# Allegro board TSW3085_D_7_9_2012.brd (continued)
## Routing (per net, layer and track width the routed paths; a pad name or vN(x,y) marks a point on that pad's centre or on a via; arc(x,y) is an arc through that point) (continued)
TCK: length 28
  BOTTOM w0.152: J15.1 R122.1 91.95,127.64 86.92,122.61 U4.26
TDI: length 43.1
  TOP w0.152: v1(92.52,100.55) 91.85,101.22 91.85,107.04 95.03,110.22 98.16,110.22 100.33,112.4 101.35,112.4 101.36,112.38 103.15,114.17 103.15,121.21 104.47,122.53 107.37,122.53 108.86,124.03 108.86,127.72 J15.9
  BOTTOM w0.152: R129.1 109.35,128.2 J15.9
TDO: length 27.6
  TOP w0.152: J15.3 101.47,127.94 101.47,119.99 99.92,118.44 99.92,113.59 98.13,111.8 v1(91.72,111.8)
  BOTTOM w0.152: R121.1 J15.3
TMS: length 39.8
  TOP w0.152: J15.5 103.33,127.26 103.33,125.63 101.88,124.18 101.88,119.56 100.38,118.06 100.38,113.56 98.07,111.25 94.72,111.25 87.72,104.25 v1(87.72,100.55)
  BOTTOM w0.152: R125.1 J15.5
TXCCLKN: length 6.3
  TOP w0.127: U1.B3 44.3,69.46
  TOP w0.152: C3.1 R15.2 44.3,73.18 44.3,69.46
TXCCLKP: length 6.3
  TOP w0.127: 44.58,69.46 44.59,69.45 44.59,69.35 44.6,69.33 U1.A3
  TOP w0.152: C4.1 45.31,74.32 45.31,73.89 R15.1 44.58,73.15 44.58,72.87 44.78,72.67 44.78,71.53 45.01,71.3 45.01,70.94 44.58,70.51 44.58,69.46
TXEN: length 92.7
  TOP w0.152: R18.2 v1(35.69,37.59)
  BOTTOM w0.152: J13.27 3.92,94.48 2.03,92.6 2.03,40.51 5.84,36.7 12.45,36.7 13.46,37.72 35.56,37.72 v1(35.69,37.59)
TXENABLE: length 38.7
  TOP w0.152: R18.1 JP2.2
  BOTTOM w0.102: 45.2,59.23 v5(45.2,60.6)
  BOTTOM w0.152: 45.2,59.23 45.2,58.69 48.77,55.12 48.77,37.46 45.85,34.54 41.4,34.54 39.37,36.58 JP2.2
TXSP1: length 66.7
  L3_PWR w0.152: v1(12.46,94.98) 15.48,94.98 34.8,114.3 38.86,114.3 38.99,114.43 40.64,114.43 40.77,114.3 43.94,114.3 45.26,115.62 67.11,115.62 v1(68.71,117.22)
  BOTTOM w0.152: J13.26 v1(12.46,94.98)
TXSP2: length 107.6
  L3_PWR w0.152: v1(94.14,106.17) 91.82,106.17 90.42,104.78 90.42,104.04 90.14,103.76 82.93,103.76 82.17,104.52 82.17,106.43 82.68,106.93 84.45,106.93 85.34,107.82 85.34,109.98 84.07,111.25 81.66,111.25 80.16,109.75 69.82,109.75 68.45,111.12 68.45,111.98 67.73,112.7 66.3,112.7 65.69,112.09 61.33,112.09 60.17,113.25 51.22,113.25 51.07,113.4 50.56,113.4 50.42,113.54 49.78,113.54 48.51,112.27 47.4,112.27 47.37,112.29 34.12,112.29 34.02,112.4 33.66,112.4 15.36,94.1 v1(12.53,94.1)
  BOTTOM w0.152: v1(12.53,94.1) 12.15,94.48 J13.28
TXSP3: length 91.3
  TOP w0.152: R2.2 7.66,88.52 8.07,88.93 8.41,88.93 9.53,90.04 9.65,90.04 11.3,91.69 13.08,91.69 v1(13.59,92.2)
  L3_PWR w0.152: v1(82.89,108.57) 83.43,108.57 83.69,108.84 83.69,110.36 83.31,110.74 81.91,110.74 80.52,109.35 66.31,109.35 64.43,111.23 60.33,111.23 58.78,112.78 51.82,112.78 50.93,111.89 47.39,111.89 47.26,112.01 34.53,112.01 34.4,111.89 34.04,111.89 14.35,92.2 v1(13.59,92.2)
TXSP4: length 87
  TOP w0.152: R3.2 8.26,87.5 11.18,90.42 12.83,90.42 v1(13.59,91.19)
  L3_PWR w0.152: v1(13.59,91.19) 14.1,91.19 34.52,111.61 46.44,111.61 46.46,111.63 46.76,111.63 46.78,111.61 58.83,111.61 59.82,110.62 64.64,110.62 66.29,108.97 81.66,108.97 82.04,109.35 82.87,109.35 v1(82.89,109.37)
TXSP5: length 116.7
  TOP w0.152: R4.2 7.62,86.49 8.13,87 8.89,87 11.94,90.04 12.95,90.04 v1(13.59,89.41)
  L3_PWR w0.152: v1(13.59,89.41) 13.11,89.89 13.11,92.64 11.68,94.06 11.68,95.1 12.34,95.76 15.37,95.76 36.2,116.59 36.2,117.16 37.01,117.98 37.47,117.98 37.52,118.03 43.92,118.03 45.87,116.08 66.88,116.08 69.16,118.36 72.34,118.36 72.82,117.88 73.23,117.88 73.71,118.36 75.56,118.36 80.07,113.86 84.77,113.86 85.85,112.78 92.58,112.78 93.98,111.38 93.98,109.98 93.6,109.6 93.6,107.52 v1(94.14,106.97)
TXSP6: length 130.4
  TOP w0.152: R1.2 7.11,90.04 6.73,90.42 5.46,90.42 5.21,90.17 5.21,86.36 5.87,85.7 8.99,85.7 11.18,87.88 13.08,87.88 v1(13.59,88.39)
  L3_PWR w0.152: v1(13.59,88.39) 13.08,88.9 12.45,88.9 12.42,88.93 12.37,88.93 11.05,90.25 11.05,95.63 11.68,96.27 15.11,96.27 35.92,117.07 35.92,117.28 36.9,118.26 37.11,118.26 37.29,118.44 44.3,118.44 46.18,116.56 66.7,116.56 70.15,120.02 70.62,120.02 70.64,119.99 71.04,119.99 71.07,120.02 75.06,120.02 80.65,114.43 85.22,114.43 86.36,113.28 92.84,113.28 94.77,111.35 94.77,105.89 94.25,105.37 v1(94.14,105.37)
USB RESET: length 9
  TOP w0.152: U3.19 106.2,115.98 106.43,115.75 110.11,115.75 SW2.2
  BOTTOM w0.152: C50.1 109.09,112.57 109.45,112.93 109.45,113.46 SW2.2
N27288443: length 13.5
  TOP w0.216: U3.16 106.91,114.03 v1(107.82,114.94)
  BOTTOM w0.216: J14.2 111.16,122.85 109.73,121.41 109.73,116.84 v1(107.82,114.94)
N27288567: length 19.1
  L3_PWR w0.508: v2(105.84,116.61) 105.49,116.61 v2(105.48,116.63) 105.14,116.63 v2(105.13,116.64) 104.73,116.64 103.33,115.23 103.33,114.25 103,113.92 v1(101.98,113.92) ; v1(101.98,113.92) 101.98,113.79 v1(101.6,113.41) 101.6,113.28 v1(101.22,112.9) ; v1(101.98,113.92) 101.98,118.49 102.87,119.38 102.87,121.89 102.92,121.89 103.3,122.28 103.3,122.83 102.92,123.22 102.87,123.22 102.87,124.08 v1(101.98,124.97)
N27288614: length 13.4
  TOP w0.152: C97.1 96,119.88 U3.4 v1(100.03,119.89) ; v1(104.11,115.09) 104.53,114.68 U3.17
  BOTTOM w0.152: v1(100.03,119.89) 100.33,119.58 101.5,119.58 102.67,118.41 102.67,115.93 103.5,115.09 v1(104.11,115.09)
N27288630: length 14.1
  TOP w0.216: v1(107.82,113.54) 107.66,113.38 U3.15
  BOTTOM w0.216: J14.3 111.25,122.05 110.36,121.16 110.36,116.59 109.47,115.7 109.47,114.55 109.22,114.3 108.59,114.3 v1(107.82,113.54)
N27836198: length 3.4
  BOTTOM w0.508: 94.59,5.22 C153.1 94.59,7.92 FB20.2
  vias: v1(96.11,8.69) v1(96.11,7.8) v1(96.75,8.94) v1(96.75,8.18) v1(97.51,8.94) v1(97.51,8.18)
N28086696: length 2.9
  TOP w0.305: 67.23,9.8 67.23,10.69 67.48,10.94 U22.1 ; U22.3 67.4,9.64
  TOP w0.508: 67.4,9.64 67.23,9.8
  vias: v2(60.99,11.07) v2(60.99,9.75) v2(61.31,11.06) v2(61.32,9.75) v3(43.1,5.64) v3(44.04,6.02) v3(45.82,7.24) v3(45.97,5.97) v3(47.35,8.43) v3(48.44,8) v3(49.07,8.38) v3(49.78,9.4) v3(50.19,7.98) v3(50.55,10.16) v3(50.83,8.38) v3(51.94,10.29) v3(52.7,9.78) v3(59.31,9.12) v3(60.71,9.02) v3(61.09,8.25) v3(61.09,7.37) v3(62.1,7.24) v3(63.25,7.62) v3(64.08,7.16) v3(64.44,7.82)
N28167010: length 3
  TOP w0.495: L3.1 C184.1 C197.2 R277.1
N28167020: length 3
  TOP w0.495: R278.1 C192.1 C184.2 L4.1
N28168739: length 3
  TOP w0.305: L1.1 C205.1 C200.2 R280.1
N28168741: length 3
  TOP w0.305: R279.1 C220.1 C205.2 L2.1
N28168902: length 3
  TOP w0.305: R303.1 C221.1 C206.2 R279.2
N28168904: length 3
  TOP w0.305: R280.2 C206.1 C217.2 R302.1
N30175128: length 4.4
  TOP w0.508: R257.2 63.14,11.94
  TOP w1.016: R128.2 62.99,13.72
N30185572: length 2.1
  TOP w0.305: R221.2 69.95,11.66
N31066293: length 3
  TOP w0.495: R296.1 C198.2 C186.1 R277.2
N31066982: length 3
  TOP w0.495: R297.1 C193.1 C186.2 R278.2
N33713354: length 2
  TOP w0.152: 49.4,72.26 C35.1 ; 49.4,72.26 R133.1 ; 49.4,72.26 R43.1
N33713380: length 1
  TOP w0.152: C34.1 R43.2
N33713396: length 4.1
  TOP w0.102: U1.A1 45.8,69.29 46.23,69.72 48.23,69.72 48.46,69.95
  TOP w0.152: 48.46,69.95 48.74,70.23 R133.2
N33713852: length 1
  BOTTOM w0.152: R44.2 R45.1
N33713873: length 4.3
  TOP w0.102: 45.8,59.55 45.8,59.23
  TOP w0.127: U1.A33 45.8,60.08 45.86,60.02 45.86,59.61 45.8,59.55
  TOP w0.152: v1(45.69,57.1) 45.8,57.2 45.8,59.23
  BOTTOM w0.152: v1(45.69,57.1) 46.13,56.67 R44.1
N33714300: length 65.2
  TOP w0.102: U1.B40 46.45,68.17 46.61,68.33 v1(48.26,68.33)
  TOP w0.152: v1(57.15,54.1) 57.28,53.98 57.28,51.82 53.85,48.39 53.85,36.45 52.83,35.43 34.8,35.43 33.66,36.58 JP3.2
  L3_PWR w0.102: 48.46,68.33 v1(48.26,68.33)
  L3_PWR w0.152: 48.46,68.33 49.02,68.33 49.4,67.95 49.4,63.37 50.42,62.36 50.8,62.36 51.05,62.1 51.05,59.84 51.21,59.69 51.56,59.69 v1(57.15,54.1)
N33806169: length 1.1
  TOP w0.305: R313.1 v1(83.19,63.91)
N33840412: length 0.9
  TOP w0.305: 91.06,67.72 91.51,67.26 U23.24
N33892115: length 0.4
  TOP w0.305: U23.18 94.77,66.25 95.05,66.52
N33970284: length 3
  TOP w0.305: R12.2 72.02,9.64 U22.4
  TOP w0.508: R12.2 R221.1
N33977043: length 2.9
  TOP w0.508: R257.1 R10.2 64.88,9.76 U13.4
N34062669: length 2.3
  TOP w0.305: C259.2 84.73,64.44 C132.2 R174.1
N34111815: length 2
  TOP w0.305: U14.6 75.88,6.8 C113.1
N34113396: length 3.3
  TOP w0.305: R159.2 76.33,13.72 76.33,13.21 75.88,12.76 U14.3
N34242338: length 2.2
  TOP w0.305: C119.1 85.4,6.33 U18.6
N34242397: length 3
  TOP w0.305: U18.3 85.4,13.41 R171.2 R176.1
N34261747: length 2.8
  TOP w0.216: R107.2 106.84,57.19 v1(106.46,57.19)
  BOTTOM w0.254: v1(106.46,57.19) 106.7,57.19 106.73,57.15 107.17,57.15 107.21,57.19 U7.3
N34261766: length 8.3
  BOTTOM w0.254: U7.2 106.98,56.69 106.8,56.51 106.8,54.75 107.44,54.1 108.2,54.1 108.76,53.55 C175.1
  BOTTOM w0.495: C175.1 108.61,52.83 C176.1
  BOTTOM w0.762: FB23.1 C176.1
N34261843: length 7.2
  BOTTOM w0.495: C256.1 105.97,54.25 C251.1 C110.1 105.71,56.09 104.32,57.48 L5.1
  BOTTOM w0.762: R293.2 C256.1
N34261894: length 9.8
  TOP w0.216: 113.28,57.15 112.39,57.15 111.38,56.13 108.97,56.13 107.41,57.69 v1(106.95,57.69)
  TOP w0.254: v1(113.32,57.19) 113.18,57.05 R108.2
  BOTTOM w0.254: U7.4 v1(106.95,57.69) ; U7.22 v1(113.32,57.19)
N34318237: length 4.1
  TOP w0.216: 49.05,110.19 48.17,109.31 U16.42
  TOP w0.495: 49.05,110.19 49.05,110.49 C127.1 49.36,112.28 C107.1
N34318365: length 3.6
  TOP w0.216: 42.29,100.71 42.42,100.71
  TOP w0.254: 42.42,100.71 43.11,101.41 U16.11
  TOP w0.305: 42.29,100.71 42.04,100.71 41.33,100.01 40.11,100.01
N34318369: length 2.9
  TOP w0.152: 42.82,100.42 42.82,100.36
  TOP w0.254: U16.12 42.82,100.42
  TOP w0.305: C52.1 42.29,100.08 42.55,100.08 42.82,100.36
N34318504:
  vias: v1(30.61,97.84)
N34318582: length 22.6
  BOTTOM w0.152: R11.2 33.5,102.44 34.19,103.12 35.43,103.12 37.92,100.63 40.36,100.63 44.83,105.11 48.74,105.11 49.05,105.41 50.65,105.41 v2(51.36,106.12)
N34318594: length 13.4
  TOP w0.254: v1(39.34,107.06) 39.93,106.48 U16.63
  BOTTOM w0.152: R9.2 31.57,100.71 31.57,103 32.69,104.11 35.28,104.11 38.23,107.06 v1(39.34,107.06)
N34318598: length 19.8
  BOTTOM w0.152: v2(40.28,106.83) 40.28,106.91 39.45,107.75 38.35,107.75 36.37,105.77 35.51,105.77 35.18,106.1 32.74,106.1 29.74,103.1 29.74,99.75 30.51,98.98 31.09,98.98 R8.2
N34318724: length 4.9
  BOTTOM w1.016: FB2.2 63.09,125.04 62.26,124.21 62.26,123.85 60.45,122.05
N34318773: length 3
  TOP w0.152: U16.37 49.94,107.54 50.47,108.07 50.47,108.3 C77.2
N34318798:
  vias: v2(45.95,99.75) v2(46.18,99.52) v2(46.3,100.1) v2(46.53,99.9)
N34318866:
  vias: v2(39.45,106.25) v2(39.67,106.02)
N34318908: length 2.3
  TOP w0.305: Y1.2 R274.2
N34318943: length 4.4
  TOP w0.305: SJP5.2 R72.1 R70.2 72.01,121.23 U26.1
N34319037: length 11.5
  TOP w0.381: U26.6 v1(67.52,122.63) ; U26.2 v1(70.29,121.98)
  TOP w0.495: FB8.1 74.93,124.08 C303.1 C302.1 74.87,121.98 U26.2
  BOTTOM w0.381: v1(67.52,122.63) 69.64,122.63 v1(70.29,121.98)
N34319101: length 5.7
  TOP w0.305: R273.2 57.91,109.73 R62.2 R61.2 60.9,109.73 Y1.1
N34319133: length 5.6
  TOP w0.305: R61.1 59.56,112.59 Y1.6
  vias: v1(62.87,117.6) v1(62.87,117.04) v1(63.53,117.04) v1(63.83,117.58)
N34319167: length 3
  TOP w0.305: R54.1 67.88,115.95 67.18,115.25
N34319169: length 1.1
  TOP w0.305: R54.2 SJP5.3
N34319278:
  vias: v1(30.61,100.1)
N34319280:
  vias: v1(30.61,102.41)
N34319320:
  vias: v1(44.3,113.18) v1(44.37,113.77) v1(45.26,114.71) v1(45.93,114.82) v2(41.94,108.74) v2(42.11,108.53) v2(43.69,110.52) v2(43.87,110.34) v2(46.4,111.08) v2(46.61,111.28)
N34319417:
  vias: v2(48.64,109.07)
N34319628: length 2.8
  TOP w0.152: C78.2 51.17,100.9 49.24,102.83 U16.26
N34337938: length 1.8
  TOP w0.152: v1(103.66,124.97) D3.1
  BOTTOM w0.152: R40.2 v1(103.66,124.97)
N34338940: length 9.6
  BOTTOM w0.61: FB26.1 100.03,114.88 101.32,114.88 101.98,115.54 101.98,117.48 101.41,118.04 U6.5 98.9,118.04 C8.1
N34339153: length 4.7
  BOTTOM w0.508: SJP3.2 104.62,112.98 104.62,113.03 104.9,113.31 104.9,115.8 104.56,116.14 U6.3
N34340024: length 10.4
  BOTTOM w0.152: J14.4 114.19,121.25 114.4,121.46 114.4,123.93 113.82,124.51 109.8,124.51 R117.1
N34341306: length 16.8
  BOTTOM w0.152: U4.35 95.25,109.37 95.5,109.63 95.5,111.68 94.13,113.06 94.13,117.96 91.04,121.06 90.53,121.06 89.92,121.67 U5.2
N34341363: length 22.2
  TOP w0.152: v1(95.76,120.65) 95.88,120.53 U3.3
  BOTTOM w0.152: U4.43 95.66,102.97 96.32,103.63 96.32,120.09 v1(95.76,120.65)
N34341376: length 20.9
  TOP w0.152: v1(85.74,106.97) 85.98,107.21 85.98,110.72 87.26,112 87.26,112.03 87.53,112.3 87.56,112.3 88.54,113.28 94.62,113.28 R20.1 96.66,115.33 U3.11
  BOTTOM w0.152: U4.18 v1(85.74,106.97)
N34341390: length 22.9
  TOP w0.152: v1(84.48,107.77) 84.02,108.23 84.02,113.35 84.98,114.3 92.61,114.3 94.31,116 95.3,116 R22.1 95.93,116.63 U3.9
  BOTTOM w0.152: U4.19 v1(84.48,107.77)
N34341426: length 24.8
  TOP w0.152: v1(95.76,121.67) 96.25,121.18 U3.2
  BOTTOM w0.152: U4.44 94.18,102.21 95.78,102.21 96.8,103.23 96.8,115.04 96.62,115.21 96.62,118.92 96.8,119.1 96.8,120.65 95.78,121.67 v1(95.76,121.67)
N34341471: length 4.3
  BOTTOM w0.152: v1(92.58,117.48) 91.31,117.48 90.91,117.08 90.91,117.07 90.61,116.76 90.47,116.76 89.92,116.21 U5.7
N34341475: length 15.2
  BOTTOM w0.152: U5.1 88.65,121.08 91.69,118.03 92.71,118.03 93.07,117.68 93.07,117.33 93.57,116.82 93.57,112.8 93.37,112.6 93.37,111.53 94.14,110.76 U4.34
N34341497: length 8.3
  BOTTOM w0.152: U5.3 91.19,123.8 91.77,124.38 96.82,124.38 v1(97.54,125.1)
N34341585: length 16.3
  TOP w0.152: v1(84.52,113.19) 85.12,113.79 92.68,113.79 93.85,114.96 95.17,114.96 95.66,115.44 R23.1 96.29,115.98 U3.10
  BOTTOM w0.152: U4.23 v1(84.52,113.19)
N34341705: length 20.4
  TOP w0.152: U3.6 96.7,118.58 96.24,118.12 96.24,118.08 v1(95.76,117.6) 95.17,117.02 94.01,117.02 92.8,115.81 85.92,115.81 82.89,112.79 v1(82.89,110.17)
N34341779: length 38.6
  TOP w0.152: v1(91.72,100.55) 91.21,101.05 91.21,107.04 94.86,110.68 98.01,110.68 102.64,115.32 v1(102.64,122.56) ; U3.1 96.61,121.83 v1(95.76,122.68)
  BOTTOM w0.152: v1(102.64,122.56) 102.51,122.68 v1(95.76,122.68)
N34341783: length 19.4
  TOP w0.152: U3.5 96.37,119.23 v1(95.76,118.62)
  BOTTOM w0.152: v1(95.76,118.62) 95.71,118.62 95.28,118.19 95.28,112.57 95.88,111.96 95.88,104.39 95.28,103.78 94.16,103.78 U4.42
N34538813: length 28.3
  BOTTOM w0.152: U4.37 86.94,107.77 77.5,117.22 v1(69.72,117.22)
N34674399: length 8.1
  TOP w0.305: U11.4 37.6,14.92 37.21,14.53 v3(36.68,14.53)
  BOTTOM w0.305: v3(40.49,9.96) 39.85,10.59 39.85,11.35 v3(36.68,14.53)
N34674443: length 7.5
  TOP w0.305: v1(38.46,16.94) 38.46,16.44 U11.1 ; R153.2 v1(39.6,21.36) C166.2 R150.1
  BOTTOM w0.305: v1(39.6,21.36) 39.6,18.21 38.46,17.07 v1(38.46,16.94)
N34674591: length 1.3
  TOP w0.305: 42.42,13.72 41.72,14.42 U11.6
N34674628:
  vias: v1(55.85,13.44) v1(55.85,12.65) v1(55.88,14.22) v1(55.88,11.81) v1(55.88,11.05) v4(54.33,10.24) v4(55.98,10.21)
N34674653: length 3.1
  TOP w0.305: U11.5 37.79,14.42 36.88,13.51 R148.1 R151.2
N34674671: length 2.5
  TOP w0.508: U12.5 57.12,13.11 57.35,12.88 C162.1
N34674884: length 0.9
  TOP w0.305: 112.01,108.33 112.25,108.57 U2.3
N34674940: length 2.8
  TOP w0.508: C215.1 98.55,106.3 99.31,105.54 U15.5
N34708918: length 1.5
  BOTTOM w0.152: J13.175 6.32,47.47 v1(6.6,47.75)
N34708920: length 1.5
  BOTTOM w0.152: v1(6.6,46.74) 6.37,46.97 J13.177
N34708959: length 2.5
  TOP w0.152: v1(6.81,95.86) R6.1
  BOTTOM w0.152: v1(6.81,95.86) 6.68,95.98 J13.21
N34714738: length 1.3
  BOTTOM w0.152: J13.38 12.35,91.98 v1(12.57,92.2)
N34714741: length 1.3
  BOTTOM w0.152: J13.40 12.28,91.48 v1(12.57,91.19)
N34722561: length 1.4
  BOTTOM w0.152: J13.50 12.14,88.98 v1(12.57,89.41)
N34722570: length 1.3
  BOTTOM w0.152: v1(12.57,88.39) 12.49,88.48 J13.52
N34728902: length 1.1
  BOTTOM w0.152: J13.47 v1(6.29,89.48)
N34729206: length 1.4
  TOP w0.152: R2.1 6.14,88.48 v1(6.31,88.48)
  BOTTOM w0.152: J13.51 v1(6.31,88.48)
N34729215: length 1.5
  BOTTOM w0.152: v1(6.35,87.5) 6.35,87.76 6.13,87.98 J13.53
N34729224: length 1.2
  BOTTOM w0.152: J13.59 v1(6.34,86.48)
N34783131: length 1.6
  BOTTOM w0.381: U6.4 98.89,116.14 C7.1
N34841492: length 3.6
  TOP w0.508: U21.4 102.92,13.71 103.16,13.46 Q1.3
N278362830: length 2.5
  TOP w0.254: D2.1 92.3,8.94 v1(93.32,8.94)
  BOTTOM w0.254: R143.1 v1(93.32,8.94)
N343181311: length 1.1
  TOP w0.495: R89.1 50.82,112.28 C127.2
N343181471: length 1.1
  TOP w0.305: C177.2 54.83,108.22 R90.1
N346744130: length 3.2
  TOP w0.305: L26.1 43.39,16.42 U11.10

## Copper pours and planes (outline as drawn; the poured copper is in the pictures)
6VIN on TOP: 2.54,99.7 2.54,107.95 19.05,107.95 19.05,102.87 12.7,102.87 12.7,99.7
6VIN on L3_PWR: 2.54,99.7 2.54,109.86 19.05,109.86 19.05,102.87 12.7,102.87 12.7,99.7
+1.2VCLK on TOP (solid shape): 68.07,31.62 68.07,23.88 64.9,23.88 64.9,30.48 63.5,31.88 63.5,33.15 64.26,33.91 65.79,33.91
+1.2VCLK on L3_PWR: 62.23,51.1 53.23,60.11 53.23,62.42 53.19,62.46 49.43,62.46 49.43,69.09 43.81,69.09 43.56,69.34 43.56,70.61 43.31,70.87 43.31,72.52 42.42,73.41 40.89,73.41 40.89,75.18 42.67,75.18 46.1,71.76 54.48,71.76 67.94,58.29 67.94,25.4 62.23,25.4
+1.2VD on TOP: 35.81,23.37 35.81,29.72 40.26,29.72 40.26,26.67 38.35,26.67 38.35,23.37
+1.2VD on L3_PWR: 34.29,23.24 34.29,60.07 38.1,63.88 38.1,75.57 40.64,75.57 40.64,71.76 43.18,71.76 43.18,70.26 43.15,70.23 43.31,70.23 43.31,69.09 43.15,68.94 43.15,68.12 42.85,67.82 42.85,60.12 44.83,58.14 44.83,57.45 44.45,57.45 44.45,23.24
+1.2VDAC on TOP (solid shape): 60.83,28.32 60.83,24.89 63.12,24.89 63.12,23.11 58.29,23.11 58.38,27.31 58.16,27.31 56.9,28.57 56.9,29.72 57.66,30.48 58.67,30.48
+1.2VDAC on L3_PWR: 43.43,60.58 46.74,57.28 46.74,51.05 52.7,45.09 52.7,25.4 60.96,25.4 60.96,49.58 51.44,59.11 50.11,59.11 50.55,59.54 50.55,61.77 49.73,62.59 48.88,62.59 48.88,67.58 47.62,68.83 43.56,68.83 43.43,68.71
+3.3V_MOD1 on TOP (solid shape): 77.6,24.13 74.04,24.13 74.04,30.23 77.6,30.23
+3.3V_MOD1 on TOP (solid shape): 78.23,65.56 78.49,65.3 78.49,63.4 77.34,63.4 77.34,65.43 77.47,65.56 77.47,66.06 78.23,66.06
+3.3V_MOD1 on L3_PWR: 69.22,49.66 69.22,59.69 66.55,62.36 66.55,85.6 66.68,85.73 91.19,85.73 91.31,85.6 91.31,80.14 71.25,80.14 71.12,80.01 71.12,66.68 73.03,64.77 76.07,64.77 77.09,65.79 78.99,65.79 78.99,61.21 75.95,61.21 75.95,49.78 77.98,47.75 77.98,25.4 72.14,25.4 72.14,46.74
+3.3V_MOD2 on TOP (solid shape): 103.66,68.73 102.39,68.73 102.39,70.51 103.66,70.51
+3.3V_MOD2 on TOP (solid shape): 82.93,24.13 79.38,24.13 79.38,30.23 82.93,30.23
+3.3V_MOD2 on L3_PWR: 79.38,76.58 79.38,76.2 77.47,76.2 77.47,50.16 79.38,48.26 79.38,25.4 84.45,25.4 84.45,72.52 95.88,72.52 96.77,71.63 96.77,67.06 104.01,67.06 104.01,72.64 101.22,72.64 100.58,73.28 100.58,73.41 97.41,76.58
+3.3VA on L6_PWR: 49.28,70.87 49.15,70.74 49.15,67.06 45.85,67.06 45.92,66.98 45.92,59.26 47.62,57.56 47.62,9.53 58.04,9.53 58.04,41.66 58.8,42.42 58.8,66.17 62.23,69.6 62.23,76.2 60.58,77.85 56.52,77.85 55.37,76.71 55.37,71.25 54.99,70.87
+3.3VCLK on TOP: 100.97,111 100.97,103.51 100.2,103.51 100.2,106.93 100.08,107.06 99.57,107.06 99.57,111
+3.3VCLK on L6_PWR: 118.11,134.62 118.11,73.03 66.68,73.03 65.72,73.98 65.72,74.49 61.21,78.99 50.93,78.99 49.28,77.34 49.28,74.3 41.91,74.3 29.21,87 29.21,134.62 ; 2 cut-outs
+3.3VD on BOTTOM (solid shape): 45.34,26.92 42.42,26.92 42.42,30.28 45.34,30.28
+3.3VD on TOP: 41.66,26.54 41.66,33.66 44.45,33.66 44.45,26.54
+3.3VD on L6_PWR: 37.97,32.89 41.91,28.96 41.91,24.77 46.1,24.77 46.1,57.39 42.93,60.56 42.93,68.96 39.88,68.96 37.97,67.06
+3.3VRF on TOP (solid shape): 83.31,15.37 82.55,14.61 81.41,14.61 78.23,11.43 76.45,11.43 76.45,12.19 77.09,12.83 77.09,14.1 76.58,14.61 76.58,17.65 75.18,17.65 74.04,18.8 74.04,21.34 83.31,21.34
+3.3VRF on L6_PWR: 118.11,50.04 118.11,55.12 117.22,56.01 112.78,56.01 112.4,55.63 112.4,55.12 109.22,55.12 108.33,56.01 105.66,56.01 103.63,58.04 90.81,58.04 88.9,59.94 80.01,59.94 79.95,60.01 67.63,60.01 62.99,55.37 62.99,23.24 74.17,12.07 84.45,12.07 84.45,19.05 76.84,19.05 72.33,23.56 72.33,38.54 72.26,38.61 72.26,49.78 92.87,49.78 94.27,51.18 108.08,51.18 108.08,49.91 113.28,49.91 113.41,50.04
+3.6V on TOP (solid shape): 113.03,109.86 112.01,109.86 111.38,109.22 108.08,109.22 108.08,110.49 113.03,110.49
+5V_MOD1 on TOP (solid shape): 89.92,24.13 86.61,24.13 86.61,30.23 89.92,30.23
+5V_MOD1 on L3_PWR: 90.17,55.12 95.88,60.83 95.88,70.87 85.09,70.87 85.09,25.4 90.17,25.4
+5V_MOD2 on TOP (solid shape): 95.25,24.13 91.95,24.13 91.95,30.23 95.25,30.23
+5V_MOD2 on TOP (solid shape): 76.33,67.59 76.71,67.59 76.71,66.83 76.2,66.83 75.95,66.57 74.17,66.57 74.17,67.84 76.07,67.84
+5V_MOD2 on TOP (solid shape): 103.38,73.43 103.12,73.18 103.12,72.92 102.36,72.92 102.36,73.3 102.11,73.56 102.11,75.34 103.38,75.34
+5V_MOD2 on L3_PWR: 104.9,67.06 104.9,73.03 101.85,73.03 101.73,73.15 101.73,74.17 98.43,77.47 76.71,77.47 76.71,66.17 75.95,65.41 73.03,65.41 71.75,66.68 71.75,79.63 71.88,79.76 94.36,79.76 97.16,82.55 103.5,82.55 109.22,76.84 109.22,65.02 105.16,60.96 105.16,52.96 96.9,44.7 96.9,25.4 91.31,25.4 91.31,53.47
+5VA_MOD on TOP (solid shape): 95.63,12.95 89.66,12.95 88.01,11.3 86.11,11.3 86.11,11.94 87.12,12.95 87.12,13.97 86.61,14.48 86.61,17.02 85.85,17.78 85.85,21.34 95.63,21.34
+5VA_MOD on L6_PWR: 94.74,13.34 88.27,13.34 88.27,19.05 90.81,19.05 99.06,27.3 99.06,46.61 103,50.55 106.93,50.55 106.93,47.62 105.28,45.97 105.28,23.88
+6V on TOP (solid shape): 117.63,108.18 114.86,108.18 114.86,109.22 117.63,109.22
+6V on TOP (solid shape): 75.31,7.87 73.66,6.22 72.64,6.22 72.64,7.49 73.41,7.49 74.8,8.89 75.31,8.89
+6V on TOP (solid shape): 80.01,6.6 78.74,6.6 78.74,7.49 78.61,7.62 76.71,7.62 76.45,7.87 76.45,8.89 80.01,8.89
+6V on TOP (solid shape): 84.84,7.87 84.2,7.24 81.53,7.24 81.53,8.25 83.69,8.25 84.2,8.76 84.84,8.76
+6V on TOP (solid shape): 89.79,6.6 88.52,6.6 88.52,7.75 86.33,7.75 86.11,7.98 86.11,8.76 89.79,8.76
+6V on TOP (solid shape): 34.16,16.64 35.18,16.64 35.43,16.38 37.08,16.38 37.59,15.88 38.73,15.88 38.73,15.49 37.21,15.49 37.08,15.37 32.38,15.37 32.38,16.89 33.91,16.89
+6V on TOP: 92.96,10.8 92.96,13.34 97.03,13.34 96.96,13.27 96.96,11.62 96.14,10.8
+6V on TOP: 106.68,119.38 106.68,116.97 109.22,116.97 109.22,119.38
+6V on TOP: 79.76,8.25 79.76,7.24 83.31,7.24 83.31,8.25
+6V on BOTTOM: 92.46,10.54 92.46,13.59 97.16,13.59 97.16,10.54
+6V on BOTTOM: 41.15,16.13 41.15,14.61 42.8,14.61 42.8,16.13
+6V on BOTTOM: 32.38,16.89 32.38,15.11 38.61,15.11 38.61,16.13 37.47,16.13 37.47,16.89
+6V on BOTTOM: 105.28,112.01 105.28,117.09 103.12,117.09 103.12,119.38 108.97,119.38 108.97,117.09 107.44,117.09 107.44,112.01
+6V on BOTTOM: 72.01,8.89 72.01,5.46 90.04,5.46 90.04,8.89
+6V on BOTTOM: 114.43,109.47 114.43,107.57 117.86,107.57 117.86,109.47
+6V on L3_PWR: 118.11,119.38 118.11,2.54 66.04,2.54 66.04,12.7 52.7,12.7 50.93,14.48 46.61,14.48 44.83,12.7 41.27,12.7 41.27,10.8 29.21,10.8 29.21,21.59 45.72,21.59 45.72,24.13 105.54,24.13 105.54,42.04 111.76,48.26 111.76,111.76 105.16,111.76 105.16,113.84 106.5,115.19 106.5,117.35 103.5,117.35 103.5,119.38
GNDA on TOP (solid shape): 67.57,112.01 68.07,112.01 68.07,110.24 66.55,110.24 66.55,111.26 65.97,111.26 65.97,112.55 67.57,112.55
GNDA on TOP: 56.52,124.46 56.52,106.68 74.93,106.68 74.93,124.46 ; 1 cut-out
GNDA on TOP: 66.68,133.98 66.68,121.29 90.17,121.29 90.17,133.98
GNDA on TOP: 0.64,82.55 0.64,111.12 8.26,118.75 27.3,118.75 27.3,136.53 120.02,136.53 120.02,82.55 ; 10 cut-outs
GNDA on TOP: 27.3,0.64 27.3,29.34 8.51,29.34 0.64,37.21 0.64,82.55 4.45,82.55 4.45,45.72 35.43,45.72 46.36,56.64 50.29,56.64 52.07,58.42 52.07,76.45 39.12,76.45 32.77,82.8 51.82,82.8 52.07,82.55 120.02,82.55 120.02,70.48 120.52,70.48 120.52,66.17 120.02,66.17 120.02,64.14 120.52,64.14 120.52,59.94 120.02,59.94 120.02,0.64 ; 3 cut-outs
GNDA on BOTTOM: 8.26,118.75 27.05,118.75 27.05,136.78 120.4,136.78 120.4,132.33 120.27,132.33 120.27,83.95 120.02,83.95 120.02,81.92 120.27,81.92 120.27,67.18 120.02,67.18 120.02,63.12 120.27,63.12 120.27,0.38 27.05,0.38 27.05,29.34 8.38,29.34 8.38,29.46 0.64,37.21 0.64,111.12 ; 4 cut-outs
GNDA on L2_GND, L5_GND, L7_GND: 8.26,118.75 27.05,118.75 27.05,136.78 120.4,136.78 120.4,132.33 120.27,132.33 120.27,83.95 120.02,83.95 120.02,81.92 120.27,81.92 120.27,67.18 120.02,67.18 120.02,63.12 120.27,63.12 120.27,0.38 27.05,0.38 27.05,29.34 8.51,29.34 0.64,37.21 0.64,111.12
GNDA on L3_PWR: 56.77,98.81 56.77,86.74 110.87,86.74 110.87,98.81
GNDA on L3_PWR: 27.81,136.14 27.81,120.27 119.38,120.27 119.38,136.14
GNDA on L3_PWR: 3.05,80.65 3.05,34.8 7.37,30.48 31.88,30.48 31.88,80.65
GNDA on L4_GND: 8.26,118.75 27.05,118.75 27.05,136.78 120.4,136.78 120.4,132.33 120.27,132.33 120.27,83.95 120.02,83.95 120.02,81.92 120.27,81.92 120.27,67.18 120.02,67.18 120.02,63.12 120.27,63.12 120.27,0.38 27.05,0.38 27.05,29.34 8.51,29.34 0.64,37.21 0.64,111.12
IN-1 on TOP (solid shape): 83.07,71.84 81.42,69.65 81.21,69.87 81.37,70.41 82.83,71.86
IP-1 on TOP (solid shape): 82.99,72.14 82.75,72.13 81.33,73.54 81.33,74.22 81.42,74.22
PLLAVDD on L6_PWR: 45.34,67.95 45.34,69.47 44.45,70.36 44.45,73.53 44.7,73.79 50.93,73.79 50.93,75.57 52.96,77.6 54.86,77.6 54.86,71.37 54.74,71.25 48.64,71.25 48.64,67.95
PWR_IN on TOP (solid shape): 18.77,96.93 13.84,96.93 13.84,101.17 18.77,101.17
PWR_IN on TOP: 109.6,13.31 105.66,17.25 101.22,17.25 101.22,14.73 104.01,14.73 104.01,10.67 99.57,10.67 98.93,10.03 98.93,8 99.31,8 99.31,3.81 107.82,3.81 109.6,5.59
PWR_IN on BOTTOM: 100.97,16.64 103.12,16.64 103.12,10.8 101.47,9.14 101.47,4.19 99.31,4.19 99.31,10.92 100.97,12.57
PWR_IN on L6_PWR: 40.64,8.25 40.64,27.94 36.07,32.51 36.07,39.5 11.63,39.5 7.95,43.18 7.95,82.88 9.53,84.46 16.51,84.46 16.51,116.84 7.37,116.84 2.54,112.01 2.54,37.46 9.53,30.48 29.21,30.48 29.21,2.54 32.51,2.54 33.4,1.65 107.57,1.65 107.57,2.54 118.11,2.54 118.11,8.25 111,8.25 111,11.43 107.57,14.86 106.55,14.86 104.39,17.02 101.09,17.02 98.93,14.86 98.93,8.25
QN-1 on TOP (solid shape): 83.04,58.48 82.81,58.45 81.26,60.03 81.31,60.63 81.42,60.63
QP-1 on TOP (solid shape): 82.98,58.19 81.42,56.06 81.14,56.06 81.19,56.61 82.77,58.24
N27836198 on BOTTOM (solid shape): 97.76,6.15 95.99,6.15 95.99,3.48 94.34,3.48 94.34,9.19 97.76,9.19
N27836198 on TOP: 97.66,12.57 98.3,12.57 98.3,12.95 102.11,12.95 102.49,12.57 102.49,10.92 101.09,10.92 100.84,11.18 99.42,11.18 98.17,9.93 98.17,6.99 95.2,6.99 95.2,10.11
N28086696 on TOP (solid shape): 67.41,9.7 68.58,9.7 68.58,9.37 66.83,7.62 66.83,6.88 66.8,6.88 66.8,6.86 60.83,6.86 60.58,7.11 60.58,8.51 60.52,8.57 59.12,8.57 58.93,8.76 58.93,9.53 60.33,9.53 60.58,9.78 61.72,9.78 61.72,8.25 61.85,8.13 65.79,8.13 65.79,9.91 67.21,9.91
N28086696 on TOP: 51.16,8 51.16,7.44 48.08,7.44 45.97,5.33 42.75,5.33 42.75,6.38 45.01,6.38 45.19,6.55 45.19,7.77 46.89,7.77 47.04,7.92 47.04,8.74 48.39,8.74 50.83,11.18 50.83,11.2 51.56,11.94 51.56,14.35 53.72,14.35 53.72,11.43 53.34,11.05 53.34,9.4 51.94,8
N28086696 on L3_PWR: 42.55,2.54 42.55,11.43 44.45,11.43 46.99,13.97 50.16,13.97 52.7,11.43 64.77,11.43 64.77,2.54
N30175128 on TOP (solid shape): 63.5,14.35 63.63,14.22 63.63,10.92 62.71,10.92 62.71,12.85 62.48,13.08 62.48,17.91 59.82,17.91 59.82,19.56 63.5,19.56
N30185572 on TOP (solid shape): 70.48,10.8 69.44,10.8 69.44,18.19 70.48,18.19
N33840412 on TOP (solid shape): 85.95,68.88 89.26,68.88 90.2,67.94 91.08,67.94 91.44,67.59 91.44,66.95 91.06,67.33 89.84,67.33 88.95,68.22 83.16,68.22 81.77,66.83 77.47,66.83 77.47,67.72 81.41,67.72 83.08,69.39 84.53,69.39 84.53,69.8 85.95,69.8
N33892115 on TOP (solid shape): 103.12,71.27 102.36,71.27 101.98,70.89 101.98,70.03 100.33,70.03 99.31,69.01 99.31,68.5 96.65,68.5 96.39,68.25 96.39,67.51 95.12,66.24 94.54,66.24 94.51,66.32 96.01,67.82 96.01,68.5 96.77,69.27 97.92,69.27 100.2,71.55 101.24,71.55 101.73,72.03 103.12,72.03
N34123238 on TOP (solid shape): 68.45,16.89 66.8,16.89 66.17,16.26 66.17,15.24 64.77,15.24 64.77,20.45 68.45,20.45
N34318798 on BOTTOM (solid shape): 47.36,99.96 45.75,98.35 45.75,97.59 46.47,96.86 45.62,96.01 45.39,96.01 44.42,96.98 44.42,97.05 42.42,99.06 43.43,100.08 44.72,98.79 46.61,100.69 46.63,100.69
N34318866 on BOTTOM (solid shape): 40.06,106.1 39.62,105.66 39.62,105.28 36.96,102.62 35.75,103.82 38.48,106.55 39.6,106.55
N34319101 on TOP (solid shape): 63.57,111.26 62.99,111.26 62.99,110.24 61.47,110.24 61.47,112.01 61.97,112.01 61.97,112.55 63.57,112.55
N34319133 on TOP (solid shape): 64.11,117.86 64.11,117.22 62.99,116.1 62.99,115.05 63.57,115.05 63.57,113.76 61.97,113.76 61.97,114.3 61.47,114.3 61.47,116.48 61.72,116.48 62.59,117.35 62.59,117.88 64.08,117.88
N34319133 on BOTTOM (solid shape): 64.8,120.73 64.08,120.73 64.08,116.79 62.59,116.79 62.59,121.89 64.8,121.89
N34319167 on TOP (solid shape): 68.07,114.3 67.57,114.3 67.57,113.76 65.97,113.76 65.97,115.05 66.55,115.05 66.55,116.08 68.07,116.08
N34319320 on BOTTOM (solid shape): 47.12,114.94 45.59,113.41 45.59,112.65 46.96,111.28 46.46,110.77 45.59,111.63 45.34,111.63 42.48,108.78 42.55,108.71 42.55,108.59 42.16,108.2 41.53,108.84 44.2,111.51 44.2,112.01 43.18,113.03 43.18,113.16 45.97,115.95 46.1,115.95
N34319417 on BOTTOM (solid shape): 51.56,109.98 50.42,108.84 49.78,109.47 49.66,109.47 48.77,108.59 48.26,109.09 49.15,109.98 49.15,110.11 47.5,111.76 48.64,112.9
N34674333 on TOP (solid shape): 42.55,20.7 45.97,20.7 45.97,18.8 42.16,18.8 42.16,18.41 40.77,18.41 40.77,25.02 42.55,25.02
N34674399 on TOP (solid shape): 46.02,10.77 44.37,10.77 44.37,8.89 40.16,8.89 40.16,12.14 46.02,12.14
N34674591 on TOP (solid shape): 45.97,13.08 41.15,13.08 41.15,14.35 45.97,14.35
N34674628 on TOP: 53.98,10.8 55.5,10.8 55.5,14.48 56.26,14.48 56.26,10.8 56.64,10.8 56.64,9.65 53.85,9.65 53.85,10.67
N34674628 on BOTTOM: 48.26,30.73 48.26,26.8 51.44,23.62 51.44,9.78 57.4,9.78 57.4,24.38 51.05,30.73
N34674884 on TOP (solid shape): 113.03,106.68 113.41,106.3 113.41,105.79 112.4,104.78 111.89,104.78 111.89,108.46 112.01,108.59 113.03,108.59
N34674886 on TOP (solid shape): 111.38,102.62 109.47,102.62 109.47,107.06 108.08,107.06 108.08,108.2 111.38,108.2
N34674946 on TOP (solid shape): 106.98,103.56 102.74,103.56 102.74,105.92 104.34,105.92 104.34,108.25 106.98,108.25
N346744130 on TOP (solid shape): 46.1,16.51 41.15,16.51 41.15,17.02 42.29,17.02 42.29,18.03 46.1,18.03

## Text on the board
BOTTOM: LAYER 8 (BOTTOM SIDE)
Ref Des/Assembly Bottom: BOTTOM SIDE
Board Geometry/Soldermask Bottom: SOLDERMASK BOTTOM
Ref Des/Silkscreen Bottom: CONNECTOR | USB | SILKSCREEN BOTTOM
User.Comments: TEXAS INSTRUMENTS | TSW3085 EVM REV D | 4. LASER CUT STENCIL WITH ELECTRO POLISH IS RECOMMENDED. TAPERED | APERTURE WALLS (5 DEGREE) TAPERING IS RECOMMENDED TO FACILITATE PASTE RELEASE. | RECOMMENDED STENCIL THICKNESS IS 127 uM FOR PITCHES > OR = 0.5MM. | IT IS RECOMMENDED TO RELEASE THE LLP PACKAGE 1 TO 2MILS INTO THE SOLDER | PASTE OR WITH MINIMUM FORCE TO AVOID CAUSING ANY POSSIBLE DAMAGE TO THE THINNER PACKAGES. | SEE NOTE 3 | TOP SIDE
TOP: LAYER 1 (TOP SIDE)
Board Geometry/Soldermask Top: SOLDERMASK TOP
Ref Des/Silkscreen Top: 2-3 = zero delay | DATACLK Trace Adjustment (SJP9-SJP12) | 1-2 = trace delay | TCK | TDO | TMS | TDI | +3.3V | MOD1 | MOD2 | +5V | SEL | LVDS DATA | J13 | CONNECTOR | H | L | +1.2VD | GND | LMK SYNC | 3.3VD | +3.3VA | DAC_RESET | +1.2VDAC | +1.2VCLK | +3.3VRF | +3.3VCLK | GAIN | +5VA | MOD | J1 | RF_LO_IN | RESET | CLKIN0 | +6V | +6V IN | LMK048XX | DAC3482 | TRF3705 | SILKSCREEN TOP
L2_GND: LAYER 2 - GND
L3_PWR: LAYER 3 - POWER
L4_GND: LAYER 4 - GND
L5_GND: LAYER 5 - GND
L6_PWR: LAYER 6 - POWER
L7_GND: LAYER 7 - GND
DIMENSION: 2 PLC'S
PAGE_OUTLINE: JV SMITH | J SETON | 01-05-12 | PASTEMASK TOP | LEADER TECH P/N: SL-11101 | RF SHIELD DRAWING | TSW3085 REV D | 1
DISPLAY_BOTTOM: PASTEMASK BOTTOM
User.5: H | MOUSE HOLE OPENING | DEPTH .O25" | NOTCHES ARE ON BOTTOM SIDE OF SHIELD | 3 PLC'S | .053 PLATED HOLE | MARK"H" | 6 PLC'S | NOTES: | 1. MATERIAL: LEADER TECH FLEX-TECH NPB SLOT LOK PRO. | 2. INSIDE HEIGHT: .500" ; OUTSIDE HEIGHT: .515" | 3. PULL TABS INCLUDED ON THE COVER. | 4. THREE MOUSE HOLES DESIGNATED IN DESIGN ON BOTTOM SIDE. | 5. FENCE DIMENSIONS DESIGNATED AT CENTERLINE. | 6. SINGLE CABITY SHIELD FRAME WITH 1 WELD. | 7. STANDARD DIMPLE SPACING: .400" | 8. LOCATOR PINS TO BE STANDARD .040 X .060 LG
User.10: FR-370HR | Pre-preg 0.011"
User.11: 02-10-12
User.12: 01-05-12 | 17. FILL 6 MIL, 8 MIL, 10 MIL AND 12 MIL VIAS WITH NON CONDUCTIVE EPOXY. | 18. FINISHED BOARDS MUST BE RoHS COMPLIANT AND SURVIVE A LEAD FREE ASSEMBLY, MAXIMUM REFLOW TEMPERATURE OF 260 DEGREE C (6 PASSES).
User.20: FIGURE | SIZE | 6.0 | 8.0 | 10.0 | 12.0 | 15.0 | 38.0 | 40.0 | 53.0 | 55.0 | 59.0 | 62.0 | 67.0 | 68.0 | 120.0 | 140.0 | 45.0 | 125.0 | DRILL CHART: TOP to BOTTOM | ALL UNITS ARE IN MILS | PLATED | NON-PLATED | QTY | 42 | 39 | 151 | 1604 | 93 | 221 | 8 | 10 | 15 | 6 | 4 | 5 | 20 | 24 | 2 | 1
User.23: 1 | 3 | 2 | * | BOTTOM SIDE
User.24: C84 | C102 | C85 | C86 | C83 | C99 | C88 | C90 | C87 | C80 | R8 | R9 | R11 | J13 | J14 | R93 | R106 | J1 | R94 | C176 | R129 | C50 | C96 | C175 | U7 | C95 | R117 | C9 | C110 | SJP3 | L5 | R293 | C251 | U6 | C256 | U8 | R40 | C155 | C154 | R122 | FB20 | R136 | C257 | C8 | C7 | R137 | R103 | C153 | R143 | U5 | C152 | R185 | U4 | C65 | C63 | FB2 | C5 | C22 | C24 | C21 | C23 | C20 | C64 | C178 | C82 | C298 | C13 | FB24 | C53 | C81 | C15 | C19 | R46 | C47 | R7 | FB22 | C6 | R45 | C40 | R44 | C42 | C180 | C89 | C181 | C26 | C43 | C30 | C128 | C179 | R125 | R121 | C249 | C17 | C48 | C49 | C38 | C36 | C25 | C41
User.25: FB23 | FB26 | FB1 | FB12 | FB18 | FB10 | FB19
